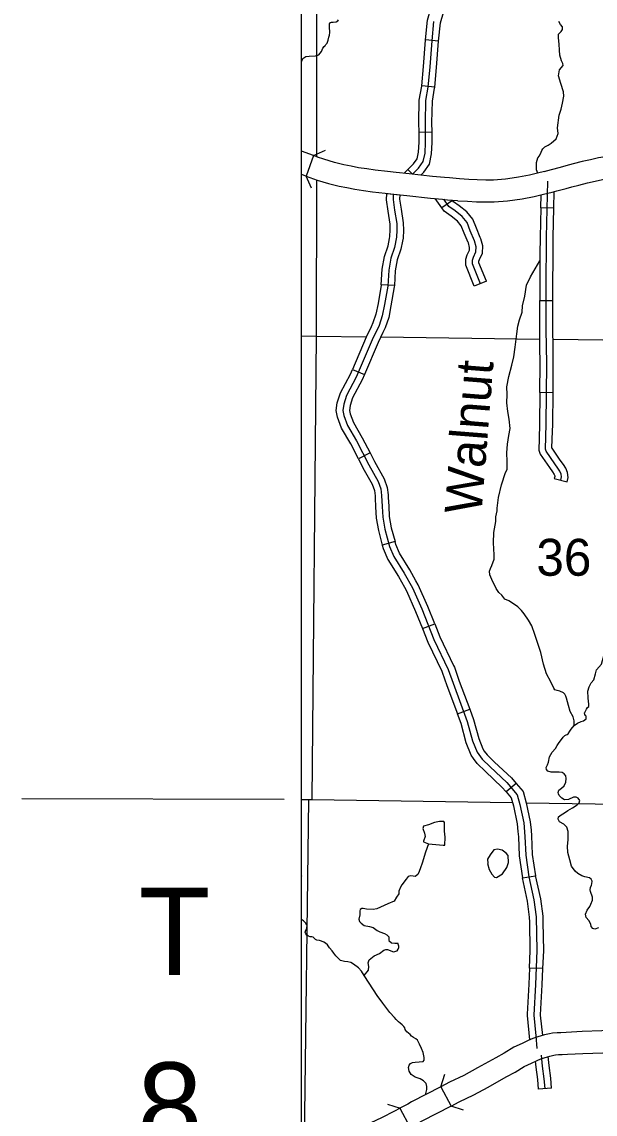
# Model space of a CAD drawing. Extents: x 813775 to 1157140, y 1757555 to 1979907.
# Drawn here: x 906132 to 919245, y 1805488 to 1830487 of the extents above; entities that cross this region are included whole.
import ezdxf

# ---------------------------------------------------------------- set-up
doc = ezdxf.new("R2010")
doc.units = 0
for name, color, linetype in [('Level 10', 7, 'Continuous'), ('Level 21', 7, 'Continuous'), ('Level 31', 7, 'Continuous'), ('Level 32', 7, 'Continuous'), ('Level 35', 7, 'Continuous'), ('Level 37', 7, 'Continuous'), ('Level 4', 7, 'Continuous'), ('Level 45', 7, 'Continuous'), ('Level 5', 7, 'Continuous'), ('R_Draft', 7, 'Continuous')]:
    doc.layers.add(name, color=color, linetype=linetype)

msp = doc.modelspace()

# ---------------------------------------------------------------- linework, layer by layer
at = {"layer": 'Level 10'}
for points in [[(912805, 1827425), (912532, 1827525)], [(912805, 1827425), (912632, 1826955)], [(912903, 1827388), (912805, 1827425)], [(920131, 1827459), (919927, 1827452), (919773, 1827439), (919596, 1827420), (919472, 1827397), (919319, 1827371), (919136, 1827329), (918950, 1827290), (918743, 1827234), (918576, 1827192), (918447, 1827154), (918241, 1827102), (918071, 1827055)], [(913667, 1827182), (913500, 1827217), (913281, 1827271), (913040, 1827344), (912894, 1827391)], [(914695, 1827040), (914499, 1827062), (914215, 1827091), (914019, 1827120), (913832, 1827148), (913667, 1827182)], [(912632, 1826955), (912532, 1826992)], [(912632, 1826955), (912890, 1826867), (913148, 1826789), (913389, 1826729), (913565, 1826692)], [(916146, 1826893), (915913, 1826915), (915803, 1826926), (915527, 1826950), (914991, 1827007), (914696, 1827040)], [(918083, 1827058), (917925, 1827022), (917743, 1826981), (917493, 1826929), (917345, 1826908), (917193, 1826890), (916918, 1826866), (916741, 1826866), (916545, 1826869), (916354, 1826880), (916139, 1826893)], [(918205, 1826573), (918369, 1826619), (918579, 1826671), (918708, 1826710), (918869, 1826750), (919067, 1826804), (919244, 1826841), (919416, 1826881), (919559, 1826905), (919668, 1826925), (919821, 1826941), (919957, 1826953), (920147, 1826959)], [(913565, 1826692), (913745, 1826655), (913947, 1826625), (914153, 1826595), (914445, 1826565), (914641, 1826543)], [(914640, 1826543), (914937, 1826510), (915479, 1826453), (915756, 1826428), (915865, 1826417), (916100, 1826395)], [(916107, 1826394), (916325, 1826381), (916528, 1826369), (916738, 1826366), (916939, 1826366), (917244, 1826392), (917410, 1826412), (917579, 1826436), (917850, 1826493), (918035, 1826534), (918193, 1826570)], [(919728, 1807412), (919397, 1807393), (918947, 1807377), (918581, 1807360), (918462, 1807352), (918379, 1807350), (918272, 1807340), (918198, 1807326), (918090, 1807302), (917932, 1807258), (917819, 1807221), (917712, 1807173), (917572, 1807107), (917385, 1807018), (917163, 1806881), (916972, 1806779), (916557, 1806545), (916243, 1806375), (915913, 1806218), (915717, 1806116)], [(915948, 1805672), (916136, 1805770), (916470, 1805929), (916799, 1806107), (917213, 1806340), (917413, 1806447), (917625, 1806578), (917786, 1806655), (917920, 1806718), (918000, 1806754), (918079, 1806780), (918212, 1806817), (918297, 1806836), (918340, 1806844), (918410, 1806850), (918487, 1806853), (918609, 1806861), (918967, 1806877), (919421, 1806893), (919757, 1806913)], [(915717, 1806116), (915046, 1805767), (914960, 1805719), (914781, 1805626)], [(915717, 1806116), (915948, 1805672)], [(915948, 1805672), (915284, 1805327), (915199, 1805279), (915011, 1805182)], [(912532, 1804929), (912674, 1804809), (912764, 1804743), (912825, 1804710), (912844, 1804703), (912897, 1804702), (912914, 1804705), (912985, 1804730), (913175, 1804813), (913370, 1804921), (913763, 1805131), (914367, 1805415), (914666, 1805566), (914781, 1805626)], [(914781, 1805626), (915011, 1805182)]]:
    msp.add_lwpolyline(points, dxfattribs=at)
at = {"layer": 'Level 21'}
for points in [[(914628, 1826545), (914622, 1826419), (914657, 1826179), (914706, 1825873)], [(914706, 1825873), (914710, 1825721), (914701, 1825557), (914653, 1825321), (914573, 1825077), (914524, 1824806), (914502, 1824441), (914426, 1824015), (914377, 1823757), (914302, 1823538), (914146, 1823210), (913782, 1822356), (913556, 1821939), (913494, 1821734), (913476, 1821592), (913494, 1821476), (913583, 1821250), (913787, 1820898), (914067, 1820351), (914284, 1819964), (914342, 1819796), (914360, 1819649), (914373, 1819396), (914386, 1819147), (914435, 1818876), (914542, 1818480), (914638, 1818254)], [(914638, 1818254), (914878, 1817868), (915064, 1817534), (915277, 1817050), (915557, 1816352), (915886, 1815662)], [(915886, 1815662), (915996, 1815349), (916321, 1814475), (916441, 1814035), (916543, 1813773), (916658, 1813613), (916840, 1813439), (917222, 1813079), (917462, 1812799), (917524, 1812576), (917613, 1812154), (917640, 1811845)], [(917640, 1811845), (917657, 1811414), (917728, 1810921), (917844, 1810392), (917897, 1810005), (917910, 1809231), (917879, 1808453), (917839, 1807751), (917888, 1807280), (917910, 1806987)]]:
    msp.add_lwpolyline(points, dxfattribs=at)
at = {"layer": 'Level 31'}
for p, q in [((918301, 1826220), (918001, 1826227)), ((914653, 1824453), (914353, 1824471)), ((914353, 1824471), (914353, 1824471)), ((917977, 1824112), (918277, 1824112)), ((913694, 1822532), (913970, 1822414)), ((918282, 1821998), (917982, 1822001)), ((917982, 1822001), (917982, 1822001)), ((914096, 1820623), (913829, 1820486)), ((918311, 1820034), (918602, 1819961)), ((914667, 1818591), (914377, 1818513)), ((915297, 1816599), (915575, 1816711)), ((916096, 1814650), (916377, 1814755)), ((917439, 1813056), (917211, 1812861)), ((917580, 1810900), (917877, 1810943)), ((918044, 1808820), (917744, 1808832))]:
    msp.add_line(p, q, dxfattribs=at)
for points in [[(918127, 1823444), (918127, 1824386), (918136, 1825559), (918165, 1826844)], [(914542, 1825527), (914552, 1825576), (914560, 1825723), (914556, 1825858), (914509, 1826156), (914471, 1826412), (914479, 1826561), (914778, 1826528)], [(914778, 1826528), (914772, 1826426), (914805, 1826202), (914856, 1825887), (914860, 1825720), (914851, 1825538), (914836, 1825466)], [(918001, 1826227), (918008, 1826528)], [(918301, 1826220), (918309, 1826602)], [(918001, 1826227), (917986, 1825561), (917983, 1825169)], [(918283, 1825167), (918286, 1825557), (918301, 1826220)], [(914353, 1824471), (914375, 1824824), (914427, 1825114), (914507, 1825360), (914542, 1825527)], [(914836, 1825466), (914798, 1825283), (914718, 1825040), (914673, 1824788), (914653, 1824453)], [(917983, 1825169), (917977, 1824387), (917977, 1824112)], [(918277, 1824112), (918277, 1824385), (918283, 1825167)], [(914353, 1824471), (914352, 1824459), (914279, 1824042), (914232, 1823796), (914163, 1823595), (914120, 1823505)], [(914653, 1824453), (914651, 1824424), (914574, 1823988), (914523, 1823718), (914441, 1823482), (914391, 1823377)], [(917983, 1823054), (917977, 1823443), (917977, 1824112)], [(918283, 1823058), (918277, 1823445), (918277, 1824112)], [(914120, 1823505), (914010, 1823271), (913694, 1822532)], [(918325, 1820371), (918125, 1820659), (918107, 1820706), (918125, 1821279), (918138, 1822670), (918127, 1823444)], [(914391, 1823377), (914283, 1823148), (913970, 1822414)], [(917982, 1822001), (917988, 1822670), (917983, 1823054)], [(918282, 1821998), (918288, 1822671), (918283, 1823058)], [(913342, 1821474), (913325, 1821590), (913347, 1821765), (913417, 1821997), (913647, 1822422), (913694, 1822532)], [(913970, 1822414), (913918, 1822291), (913695, 1821880), (913641, 1821703), (913627, 1821594), (913639, 1821519)], [(917982, 1822001), (917975, 1821282), (917965, 1820949)], [(918265, 1820939), (918275, 1821276), (918282, 1821998)], [(913829, 1820486), (913655, 1820826), (913447, 1821184), (913348, 1821437), (913342, 1821474)], [(913639, 1821519), (913640, 1821516), (913718, 1821315), (913919, 1820970), (914096, 1820623)], [(917965, 1820949), (917957, 1820681), (917991, 1820589), (918202, 1820285), (918271, 1820185), (918308, 1820130), (918321, 1820097), (918323, 1820081), (918311, 1820034)], [(918602, 1819961), (918627, 1820060), (918615, 1820172), (918574, 1820272), (918519, 1820353), (918448, 1820456), (918259, 1820730), (918258, 1820731), (918265, 1820939)], [(913829, 1820486), (913934, 1820280), (914147, 1819903), (914195, 1819762), (914210, 1819636), (914213, 1819584)], [(914096, 1820623), (914199, 1820422), (914422, 1820026), (914489, 1819829), (914509, 1819662), (914512, 1819599)], [(918457, 1819998), (918475, 1820071), (918468, 1820135), (918441, 1820201), (918395, 1820269), (918325, 1820371)], [(914213, 1819584), (914223, 1819388), (914237, 1819129), (914289, 1818843), (914377, 1818513)], [(914512, 1819599), (914523, 1819404), (914536, 1819164), (914582, 1818908), (914667, 1818591)], [(914377, 1818513), (914400, 1818431), (914505, 1818185), (914749, 1817791), (914884, 1817549)], [(915146, 1817696), (915007, 1817944), (914772, 1818324), (914684, 1818529), (914667, 1818591)], [(915575, 1816711), (915416, 1817108), (915199, 1817601), (915146, 1817696)], [(914884, 1817549), (914930, 1817467), (915139, 1816992), (915297, 1816599)], [(915575, 1816711), (915695, 1816412), (916006, 1815757)], [(915297, 1816599), (915420, 1816292), (915736, 1815629)], [(916006, 1815757), (916025, 1815719), (916137, 1815400), (916377, 1814755)], [(915736, 1815629), (915747, 1815605), (915855, 1815298), (916096, 1814650)], [(916377, 1814755), (916464, 1814521), (916583, 1814082), (916676, 1813845), (916709, 1813799)], [(916466, 1813624), (916410, 1813701), (916298, 1813988), (916178, 1814429), (916096, 1814650)], [(916709, 1813799), (916772, 1813712), (916944, 1813547), (917331, 1813182), (917439, 1813056)], [(917211, 1812861), (917113, 1812975), (916737, 1813330), (916545, 1813514), (916466, 1813624)], [(917439, 1813056), (917597, 1812871), (917670, 1812612), (917762, 1812176), (917778, 1811985)], [(917211, 1812861), (917326, 1812726), (917378, 1812541), (917464, 1812132), (917479, 1811959)], [(917479, 1811959), (917490, 1811836), (917508, 1811400), (917580, 1810900)], [(917778, 1811985), (917789, 1811855), (917807, 1811428), (917877, 1810943)], [(917876, 1810948), (917992, 1810418), (918047, 1810017), (918049, 1809884)], [(917749, 1809879), (917747, 1809994), (917696, 1810366), (917581, 1810894), (917580, 1810900)], [(917744, 1808832), (917760, 1809233), (917749, 1809879)], [(918049, 1809884), (918060, 1809229), (918044, 1808820)], [(917744, 1808832), (917729, 1808460), (917691, 1807780)], [(918044, 1808820), (918029, 1808446), (917990, 1807763)], [(917691, 1807780), (917689, 1807747), (917747, 1807188)], [(917990, 1807763), (917990, 1807754), (918038, 1807288)]]:
    msp.add_lwpolyline(points, dxfattribs=at)
at = {"layer": 'Level 32'}
for p, q in [((915664, 1830047), (915366, 1830077)), ((915577, 1828995), (915278, 1829024)), ((915516, 1827960), (915216, 1827957)), ((915067, 1826999), (914960, 1827105)), ((918248, 1806084), (917949, 1806060))]:
    msp.add_line(p, q, dxfattribs=at)
for points in [[(915366, 1830077), (915411, 1830522), (915495, 1830818), (915605, 1831012), (915719, 1831141)], [(915664, 1830047), (915707, 1830465), (915774, 1830702), (915850, 1830837), (915943, 1830942)], [(915067, 1826999), (915208, 1827141), (915315, 1827292), (915355, 1827483), (915368, 1827728), (915363, 1828181), (915372, 1828683), (915426, 1828991), (915470, 1829454), (915514, 1830054), (915559, 1830494)], [(915278, 1829024), (915321, 1829466), (915365, 1830067), (915366, 1830077)], [(915577, 1828995), (915619, 1829441), (915664, 1830041), (915664, 1830047)], [(915216, 1827957), (915213, 1828181), (915223, 1828697), (915277, 1829011), (915278, 1829024)], [(915516, 1827960), (915513, 1828180), (915522, 1828669), (915574, 1828971), (915577, 1828995)], [(914875, 1827020), (915093, 1827238), (915174, 1827353), (915205, 1827503), (915218, 1827731), (915216, 1827957)], [(915258, 1826979), (915323, 1827044), (915455, 1827231), (915504, 1827464), (915518, 1827724), (915516, 1827960)], [(917949, 1806060), (917931, 1806282), (917894, 1806567), (917882, 1806701)], [(918098, 1806072), (918080, 1806298), (918043, 1806583), (918021, 1806837)], [(918248, 1806084), (918229, 1806313), (918193, 1806599), (918174, 1806807)]]:
    msp.add_lwpolyline(points, dxfattribs=at)
at = {"layer": 'Level 35'}
for points in [[(913050, 1829920), (913112, 1830001), (913140, 1830066), (913156, 1830137), (913171, 1830184), (913174, 1830246), (913166, 1830370), (913165, 1830416), (913172, 1830445), (913190, 1830475), (913212, 1830481), (913256, 1830482), (913323, 1830487), (913358, 1830509), (913374, 1830531)], [(918407, 1830120), (918407, 1830206), (918469, 1830268), (918498, 1830312), (918498, 1830372), (918449, 1830426), (918418, 1830494)], [(912532, 1829572), (912537, 1829587), (912559, 1829651), (912627, 1829690), (912705, 1829705), (912852, 1829709), (912921, 1829729), (912984, 1829807), (913018, 1829888), (913050, 1829920), (913068, 1829938)], [(918495, 1828623), (918526, 1828787), (918519, 1828882), (918459, 1829074), (918410, 1829248), (918433, 1829385), (918511, 1829486), (918508, 1829532), (918475, 1829594), (918441, 1829724), (918428, 1829835), (918420, 1829975), (918407, 1830120)], [(917932, 1827023), (917906, 1827100), (917900, 1827266), (917937, 1827374), (917970, 1827424), (918012, 1827507), (918024, 1827546), (918048, 1827582), (918097, 1827623), (918169, 1827662), (918237, 1827711), (918356, 1827810), (918400, 1827932), (918387, 1828058), (918420, 1828351), (918467, 1828488), (918495, 1828623)], [(917476, 1823522), (917518, 1823670), (917577, 1823844), (917585, 1823991), (917634, 1824206), (917673, 1824462), (917763, 1824654), (917982, 1825018)], [(917228, 1822134), (917267, 1822372), (917342, 1822629), (917386, 1822823), (917414, 1823038), (917450, 1823349), (917476, 1823522)], [(917269, 1821017), (917298, 1821183), (917282, 1821390), (917246, 1821567), (917228, 1821771), (917230, 1821955), (917228, 1822134)], [(917003, 1819357), (917031, 1819603), (917101, 1819893), (917197, 1820170), (917230, 1820245), (917236, 1820292), (917230, 1820424), (917223, 1820623), (917238, 1820825), (917269, 1821017)], [(916879, 1818046), (916936, 1818192), (916933, 1818288), (916923, 1818565), (916925, 1818803), (916974, 1819051), (916972, 1819160), (917005, 1819297), (917003, 1819357)], [(917717, 1816797), (917618, 1816941), (917559, 1817018), (917474, 1817099), (917352, 1817184), (917274, 1817233), (917176, 1817275), (917109, 1817365), (917042, 1817425), (916980, 1817518), (916879, 1817723), (916835, 1817829), (916827, 1817914), (916848, 1817979), (916879, 1818046)], [(918229, 1815380), (918133, 1815562), (918066, 1815785), (918006, 1816052), (917869, 1816466), (917794, 1816663), (917717, 1816797)], [(919212, 1815429), (919254, 1815566), (919274, 1815657), (919387, 1815788), (919455, 1816011), (919511, 1816183), (919539, 1816246), (919581, 1816357), (919614, 1816448), (919700, 1816680)], [(919010, 1814677), (919044, 1814756), (919070, 1814792), (919098, 1814816), (919103, 1814880), (919090, 1814932), (919088, 1815018), (919075, 1815168), (919108, 1815269), (919152, 1815357), (919212, 1815429)], [(918767, 1814381), (918767, 1814425), (918764, 1814492), (918741, 1814578), (918676, 1814704), (918632, 1814839), (918588, 1815007), (918578, 1815051), (918552, 1815098), (918519, 1815132), (918441, 1815170), (918376, 1815183), (918325, 1815202), (918299, 1815240), (918229, 1815380)], [(918982, 1814492), (919040, 1814533), (919043, 1814564), (919036, 1814594), (919023, 1814613), (919009, 1814638), (919004, 1814675), (919010, 1814677)], [(918153, 1813480), (918180, 1813546), (918204, 1813664), (918265, 1813769), (918336, 1813855), (918375, 1813928), (918420, 1813995), (918451, 1814033), (918515, 1814119), (918551, 1814153), (918581, 1814170), (918608, 1814180), (918625, 1814195), (918664, 1814254), (918693, 1814300), (918767, 1814381), (918842, 1814435), (918928, 1814476), (918982, 1814492)], [(918529, 1812123), (918433, 1812180), (918402, 1812242), (918407, 1812289), (918467, 1812338), (918542, 1812387), (918622, 1812434), (918728, 1812496), (918831, 1812566), (918881, 1812615), (918896, 1812664), (918857, 1812721), (918813, 1812742), (918749, 1812745), (918632, 1812688), (918542, 1812685), (918480, 1812719), (918423, 1812778), (918405, 1812817), (918402, 1812851), (918418, 1812900), (918477, 1812952), (918539, 1813001), (918578, 1813089), (918583, 1813169), (918575, 1813229), (918537, 1813278), (918487, 1813307), (918423, 1813317), (918345, 1813314), (918239, 1813314), (918159, 1813338), (918131, 1813374), (918128, 1813418), (918153, 1813480)], [(915436, 1811675), (915771, 1811644), (915808, 1811644), (915816, 1811828), (915798, 1811964), (915803, 1812045), (915801, 1812108), (915796, 1812163), (915783, 1812184), (915682, 1812184), (915569, 1812166), (915430, 1812113), (915322, 1812080), (915307, 1812022), (915345, 1811921), (915360, 1811845), (915317, 1811739), (915317, 1811722), (915436, 1811675)], [(918937, 1810941), (918850, 1810994), (918785, 1811051), (918707, 1811162), (918669, 1811310), (918619, 1811478), (918614, 1811623), (918625, 1811766), (918627, 1811848), (918627, 1811955), (918594, 1812056), (918529, 1812123)], [(915436, 1811675), (915368, 1811486), (915290, 1811234), (915252, 1811125), (915222, 1811040), (915189, 1810974), (915131, 1810926), (915086, 1810931), (915023, 1810944), (914968, 1810929), (914920, 1810865), (914821, 1810734), (914789, 1810686), (914753, 1810593), (914753, 1810530), (914705, 1810454), (914647, 1810363), (914501, 1810298), (914254, 1810184), (914171, 1810175), (914017, 1810180), (913939, 1810196), (913906, 1810196), (913868, 1810175), (913866, 1810138), (913861, 1810047), (913843, 1809951), (913855, 1809895), (913896, 1809857), (913959, 1809809), (914082, 1809780), (914171, 1809758), (914256, 1809692), (914317, 1809662), (914423, 1809624), (914481, 1809594), (914523, 1809546), (914526, 1809464)], [(916784, 1811228), (916822, 1811084), (916880, 1810983), (916940, 1810913), (916986, 1810905), (917127, 1810986), (917228, 1811135), (917263, 1811251), (917258, 1811410), (917207, 1811460), (917122, 1811526), (917013, 1811553), (916930, 1811536), (916844, 1811425), (916786, 1811326), (916789, 1811223)], [(912532, 1810920), (912535, 1810933), (912532, 1810942)], [(919320, 1809749), (919237, 1809721), (919193, 1809734), (919154, 1809781), (919147, 1809838), (919103, 1809921), (919043, 1809988), (919022, 1810068), (919061, 1810156), (919126, 1810237), (919144, 1810294), (919183, 1810389), (919185, 1810457), (919136, 1810584), (919131, 1810625), (919141, 1810672), (919165, 1810726), (919170, 1810760), (919180, 1810819), (919152, 1810863), (919113, 1810897), (919012, 1810920), (918937, 1810941)], [(912626, 1809856), (912574, 1809911), (912532, 1809945)], [(913228, 1809226), (913170, 1809297), (913122, 1809361), (913074, 1809405), (913041, 1809427), (912987, 1809448), (912943, 1809461), (912881, 1809472), (912847, 1809487), (912818, 1809512), (912797, 1809535), (912768, 1809549), (912726, 1809549), (912688, 1809560), (912650, 1809582), (912628, 1809613), (912616, 1809652), (912631, 1809695), (912648, 1809745), (912654, 1809771), (912655, 1809795), (912648, 1809820), (912626, 1809856)], [(914526, 1809464), (914584, 1809406), (914662, 1809398), (914728, 1809401)], [(913964, 1808660), (913898, 1808763), (913831, 1808838), (913715, 1808919), (913660, 1808958), (913588, 1808972), (913512, 1808983), (913423, 1809004), (913356, 1809067), (913317, 1809112), (913269, 1809176), (913228, 1809226)], [(913964, 1808660), (914062, 1808785), (914065, 1808866), (914057, 1808949), (914075, 1809020), (914188, 1809113), (914312, 1809168), (914413, 1809242), (914458, 1809254), (914498, 1809254), (914634, 1809206), (914713, 1809224), (914740, 1809267), (914755, 1809305), (914753, 1809335), (914728, 1809401)], [(914658, 1807702), (914549, 1807815), (914385, 1808027), (914256, 1808206), (914077, 1808489), (913964, 1808660)], [(915145, 1807212), (915091, 1807241), (915047, 1807272), (915012, 1807310), (914939, 1807374), (914911, 1807406), (914896, 1807429), (914890, 1807464), (914868, 1807493), (914830, 1807535), (914786, 1807571), (914745, 1807599), (914692, 1807657), (914658, 1807702)], [(915364, 1805932), (915397, 1806051), (915392, 1806122), (915382, 1806192), (915316, 1806253), (915241, 1806298), (915130, 1806334), (915039, 1806394), (914989, 1806470), (914978, 1806556), (914989, 1806611), (915024, 1806651), (915069, 1806667), (915130, 1806677), (915311, 1806692), (915336, 1806727), (915331, 1806788), (915311, 1806899), (915276, 1806990), (915226, 1807090), (915180, 1807181), (915145, 1807212)]]:
    msp.add_lwpolyline(points, dxfattribs=at)
at = {"layer": 'Level 37'}
for points in [[(912805, 1827425), (913077, 1827550)], [(912757, 1826683), (912632, 1826955)], [(915717, 1806116), (915807, 1806402)], [(914497, 1805718), (914783, 1805627)], [(916234, 1805582), (915948, 1805672)]]:
    msp.add_lwpolyline(points, dxfattribs=at)
at = {"layer": 'Level 4'}
for points in [[(906132, 1812713), (912132, 1812696)], [(912532, 1812687), (912692, 1812687), (912766, 1812686), (917357, 1812618)], [(917669, 1812613), (921340, 1812559)]]:
    msp.add_lwpolyline(points, dxfattribs=at)
at = {"layer": 'Level 45'}
for p, q in [((915985, 1826397), (915738, 1826227)), ((916759, 1824549), (916481, 1824437))]:
    msp.add_line(p, q, dxfattribs=at)
for points in [[(915738, 1826227), (915589, 1826443)], [(916620, 1824493), (916438, 1824945), (916438, 1825030), (916460, 1825101), (916518, 1825225), (916522, 1825341), (916487, 1825474), (916389, 1825705), (916314, 1825892), (916203, 1826030), (916043, 1826159), (915896, 1826261), (915783, 1826425)], [(915985, 1826397), (915978, 1826406)], [(916341, 1825433), (916250, 1825648), (916183, 1825815), (916096, 1825923), (915953, 1826039), (915788, 1826154), (915738, 1826227)], [(916618, 1825550), (916528, 1825763), (916444, 1825969), (916309, 1826137), (916133, 1826279), (916004, 1826368), (915985, 1826397)], [(916481, 1824437), (916288, 1824916), (916288, 1825053), (916320, 1825155), (916369, 1825261), (916372, 1825324), (916345, 1825426), (916341, 1825433)], [(916759, 1824549), (916588, 1824975), (916588, 1825007), (916600, 1825047), (916667, 1825190), (916673, 1825358), (916629, 1825523), (916618, 1825550)]]:
    msp.add_lwpolyline(points, dxfattribs=at)
at = {"layer": 'Level 5'}
for points in [[(912882, 1833970), (912871, 1827400)], [(912870, 1826874), (912864, 1823294)], [(912532, 1823301), (912864, 1823294)], [(912864, 1823294), (912766, 1812686)], [(912864, 1823294), (914013, 1823280)], [(914343, 1823275), (917980, 1823228)], [(918281, 1823224), (923402, 1823158)], [(912692, 1812687), (912593, 1804877)]]:
    msp.add_lwpolyline(points, dxfattribs=at)
at = {"layer": 'R_Draft'}
msp.add_lwpolyline([(912532, 1880709), (1062535, 1880709), (1062535, 1798155), (912532, 1798155)], close=True, dxfattribs=at)

# ---------------------------------------------------------------- texts
at = {"layer": 'Level 35'}
msp.add_text('Walnut', height=844.8, rotation=85.4754, dxfattribs=at).set_placement((916643, 1819198))
at = {"layer": 'Level 5'}
msp.add_text('36', height=844.8, dxfattribs=at).set_placement((917901, 1817810))
at = {"layer": 'R_Draft'}
for s, p in [('T', (908807, 1808671)), ('8', (908774, 1804671))]:
    msp.add_text(s, height=2000, dxfattribs=at).set_placement(p)

doc.saveas('drawing.dxf')
